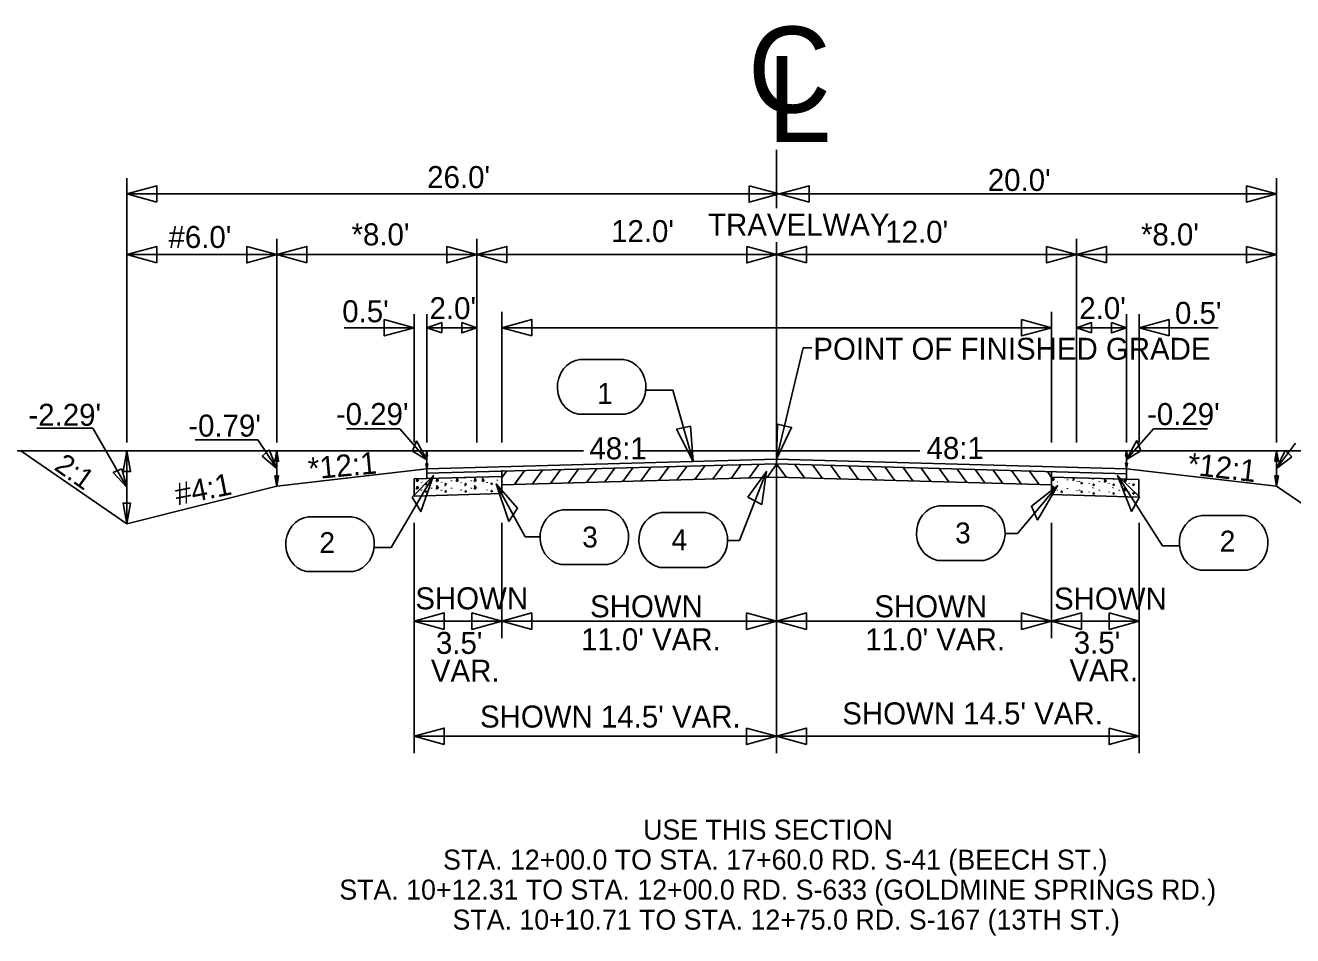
# Model space of a CAD drawing. Extents: x 2061536 to 2063199, y 948597 to 949645.
# Drawn here: x 2062001 to 2062634, y 948998 to 949454 of the extents above; entities that cross this region are included whole.
import ezdxf

# ---------------------------------------------------------------- set-up
doc = ezdxf.new("R2010")
doc.units = 0
for name, color, linetype in [('Default', 7, 'Continuous'), ('RD_TX_Drainage', 7, 'Continuous'), ('RD_TX_TypSect', 7, 'Continuous'), ('RD_XS_Base', 7, 'Continuous'), ('RD_XS_EarthShd', 7, 'Continuous'), ('RD_XS_Pave', 7, 'Continuous')]:
    doc.layers.add(name, color=color, linetype=linetype)

msp = doc.modelspace()

# ---------------------------------------------------------------- linework, layer by layer
at = {"layer": 'Default'}
for p, q in [((2062376.29, 949362.08), (2062376.29, 949391.39)), ((2062051.29, 949245.07), (2062051.29, 949377.17)), ((2062626.29, 949245.07), (2062626.29, 949377.17)), ((2062119.72, 949369.28), (2062051.29, 949369.28)), ((2062377.53, 949369.28), (2062119.72, 949369.28)), ((2062377.53, 949369.28), (2062626.29, 949369.28)), ((2062126.29, 949245.07), (2062126.29, 949346.82)), ((2062226.29, 949245.07), (2062226.29, 949346.82)), ((2062526.29, 949245.07), (2062526.29, 949346.82)), ((2062376.29, 949340.85), (2062376.29, 949345.1)), ((2062376.29, 949306.44), (2062376.29, 949340.85)), ((2062126.29, 949338.93), (2062051.29, 949338.93)), ((2062226.29, 949338.93), (2062126.29, 949338.93)), ((2062376.29, 949338.93), (2062226.29, 949338.93)), ((2062376.29, 949338.93), (2062526.29, 949338.93)), ((2062526.29, 949338.93), (2062626.29, 949338.93)), ((2062195.04, 949245.07), (2062195.04, 949309.2)), ((2062201.29, 949245.07), (2062201.29, 949309.2)), ((2062238.79, 949245.07), (2062238.79, 949310.28)), ((2062513.79, 949245.07), (2062513.79, 949310.28)), ((2062551.29, 949245.07), (2062551.29, 949309.2)), ((2062557.54, 949245.07), (2062557.54, 949309.2)), ((2062195.04, 949302.39), (2062159.95, 949302.39)), ((2062195.04, 949302.39), (2062167.38, 949302.39)), ((2062226.29, 949302.39), (2062201.29, 949302.39)), ((2062238.79, 949302.39), (2062513.79, 949302.39)), ((2062376.29, 949295.45), (2062376.29, 949306.44)), ((2062526.29, 949302.39), (2062551.29, 949302.39)), ((2062557.54, 949302.39), (2062597.15, 949302.39)), ((2062376.29, 949089.68), (2062376.29, 949295.45)), ((2062376.29, 949236.65), (2062389.59, 949292.31)), ((2062389.59, 949292.31), (2062393.83, 949292.31)), ((2062324.32, 949271.16), (2062310.37, 949271.16)), ((2062334.47, 949235.47), (2062324.32, 949271.16)), ((2062006.29, 949252.16), (2062034.34, 949252.16)), ((2062034.34, 949252.16), (2062051.29, 949222.58)), ((2062187.82, 949251.78), (2062161.2, 949251.78)), ((2062187.82, 949251.78), (2062201.29, 949236.25)), ((2062564.77, 949251.78), (2062551.29, 949236.43)), ((2062564.77, 949251.78), (2062591.72, 949251.78)), ((2062116.79, 949246.28), (2062085.44, 949246.28)), ((2062116.79, 949246.28), (2062126.29, 949231.96)), ((2062635.79, 949244.68), (2062626.29, 949231.96)), ((2062199.54, 949240.77), (2061643.36, 949240.77)), ((2062051.29, 949204.39), (2062051.29, 949240.77)), ((2062126.29, 949223.14), (2062126.29, 949240.77)), ((2062279.64, 949240.77), (2062199.54, 949240.77)), ((2062201.29, 949231.74), (2062201.29, 949240.77)), ((2062376.29, 949240.77), (2062307.2, 949240.77)), ((2062376.29, 949240.77), (2062447.94, 949240.77)), ((2062476.17, 949240.77), (2062557.9, 949240.77)), ((2062551.29, 949231.74), (2062551.29, 949240.77)), ((2062555.37, 949240.77), (2063173.98, 949240.77)), ((2062626.29, 949223.14), (2062626.29, 949240.77)), ((2062204.67, 949228.55), (2062183.53, 949192.56)), ((2062357.77, 949196.05), (2062371.14, 949230.57)), ((2062546.7, 949228.41), (2062569.22, 949193.26)), ((2062250.57, 949197.82), (2062236.04, 949224.3)), ((2062496.66, 949199.53), (2062516.81, 949223.38)), ((2062195.04, 949147.22), (2062195.04, 949204.75)), ((2062238.79, 949147.22), (2062238.79, 949204.75)), ((2062513.79, 949147.22), (2062513.79, 949204.75)), ((2062557.54, 949147.22), (2062557.54, 949204.75)), ((2062257.95, 949197.82), (2062250.57, 949197.82)), ((2062351.69, 949196.05), (2062357.77, 949196.05)), ((2062490.7, 949199.53), (2062496.66, 949199.53)), ((2062183.53, 949192.56), (2062175.04, 949192.56)), ((2062569.22, 949193.26), (2062577.71, 949193.26)), ((2062376.29, 949155.62), (2062195.04, 949155.62)), ((2062376.29, 949155.62), (2062557.54, 949155.62)), ((2062195.04, 949089.68), (2062195.04, 949147.22)), ((2062557.54, 949089.68), (2062557.54, 949147.22)), ((2062376.29, 949098.08), (2062195.04, 949098.08)), ((2062376.23, 949098.08), (2062557.54, 949098.08))]:
    msp.add_line(p, q, dxfattribs=at)
for points in [[(2062066.29, 949365.15), (2062051.29, 949369.28), (2062066.29, 949373.4)], [(2062362.53, 949373.4), (2062377.53, 949369.28), (2062362.53, 949365.15)], [(2062392.53, 949365.15), (2062377.53, 949369.28), (2062392.53, 949373.4)], [(2062611.29, 949373.4), (2062626.29, 949369.28), (2062611.29, 949365.15)], [(2062066.29, 949334.8), (2062051.29, 949338.93), (2062066.29, 949343.05)], [(2062111.29, 949343.05), (2062126.29, 949338.93), (2062111.29, 949334.8)], [(2062141.29, 949334.8), (2062126.29, 949338.93), (2062141.29, 949343.05)], [(2062211.29, 949343.05), (2062226.29, 949338.93), (2062211.29, 949334.8)], [(2062241.29, 949334.8), (2062226.29, 949338.93), (2062241.29, 949343.05)], [(2062361.29, 949343.05), (2062376.29, 949338.93), (2062361.29, 949334.8)], [(2062391.29, 949334.8), (2062376.29, 949338.93), (2062391.29, 949343.05)], [(2062511.29, 949343.05), (2062526.29, 949338.93), (2062511.29, 949334.8)], [(2062541.29, 949334.8), (2062526.29, 949338.93), (2062541.29, 949343.05)], [(2062611.29, 949343.05), (2062626.29, 949338.93), (2062611.29, 949334.8)], [(2062180.04, 949306.52), (2062195.04, 949302.39), (2062180.04, 949298.27)], [(2062253.79, 949298.27), (2062238.79, 949302.39), (2062253.79, 949306.52)], [(2062498.79, 949306.52), (2062513.79, 949302.39), (2062498.79, 949298.27)], [(2062572.54, 949298.27), (2062557.54, 949302.39), (2062572.54, 949306.52)], [(2062333.12, 949253.11), (2062334.47, 949235.47), (2062326.22, 949251.59)], [(2062376.78, 949254.19), (2062376.29, 949236.65), (2062383.79, 949252.52)], [(2062196.19, 949245.8), (2062201.29, 949236.25), (2062194.24, 949240.71)], [(2062556.45, 949245.95), (2062551.29, 949236.43), (2062558.37, 949240.84)], [(2062118.94, 949238.19), (2062126.29, 949231.96), (2062122.47, 949241.26)], [(2062633.98, 949237.77), (2062626.29, 949231.96), (2062630.63, 949241.03)], [(2062048.78, 949231.88), (2062051.29, 949222.58), (2062044.5, 949229.99)], [(2062193.99, 949217.61), (2062204.67, 949228.55), (2062198.27, 949210.41)], [(2062361.92, 949217.58), (2062371.14, 949230.57), (2062368.94, 949214.06)], [(2062557.8, 949217.89), (2062546.7, 949228.41), (2062553.8, 949210.53)], [(2062242.37, 949205.49), (2062236.04, 949224.3), (2062246.7, 949212.17)], [(2062506.69, 949206.08), (2062516.81, 949223.38), (2062503.65, 949213.12)], [(2062210.04, 949151.5), (2062195.04, 949155.62), (2062210.04, 949159.75)], [(2062223.79, 949159.75), (2062238.79, 949155.62), (2062223.79, 949151.5)], [(2062253.79, 949151.5), (2062238.79, 949155.62), (2062253.79, 949159.75)], [(2062361.23, 949159.75), (2062376.23, 949155.62), (2062361.23, 949151.5)], [(2062391.23, 949151.5), (2062376.23, 949155.62), (2062391.23, 949159.75)], [(2062498.79, 949159.75), (2062513.79, 949155.62), (2062498.79, 949151.5)], [(2062528.79, 949151.5), (2062513.79, 949155.62), (2062528.79, 949159.75)], [(2062542.54, 949159.75), (2062557.54, 949155.62), (2062542.54, 949151.5)], [(2062210.04, 949093.96), (2062195.04, 949098.08), (2062210.04, 949102.21)], [(2062361.23, 949102.21), (2062376.23, 949098.08), (2062361.23, 949093.96)], [(2062391.23, 949093.96), (2062376.23, 949098.08), (2062391.23, 949102.21)], [(2062542.54, 949102.21), (2062557.54, 949098.08), (2062542.54, 949093.96)]]:
    msp.add_lwpolyline(points, close=True, dxfattribs=at)
for points in [[(2062277.84, 949286.44), (2062299.75, 949286.44)], [(2062300.43, 949259.09), (2062277.16, 949259.09)], [(2062457.42, 949213.39), (2062479.33, 949213.39)], [(2062163.91, 949207.83), (2062141.99, 949207.83)], [(2062291.07, 949211.34), (2062269.16, 949211.34)], [(2062318.61, 949209.91), (2062340.52, 949209.91)], [(2062588.84, 949208.54), (2062610.76, 949208.54)], [(2062268.48, 949184), (2062291.75, 949184)], [(2062341.2, 949182.57), (2062317.93, 949182.57)], [(2062480.01, 949186.04), (2062456.74, 949186.04)], [(2062611.43, 949181.19), (2062588.16, 949181.19)], [(2062141.32, 949180.49), (2062164.59, 949180.49)]]:
    msp.add_lwpolyline(points, dxfattribs=at)
for centre, major_axis, start_param, end_param in [((2062279.17, 949272.71), (0, 13.8), 6.17662, 9.263617), ((2062298.42, 949272.71), (0, 13.8), 3.302754, 6.389751), ((2062458.75, 949199.66), (0, 13.8), 6.17662, 9.263617), ((2062478, 949199.66), (0, 13.8), 3.302754, 6.389751), ((2062143.33, 949194.11), (0, -13.8), 3.035027, 6.122024), ((2062162.57, 949194.11), (0, -13.8), 0.161161, 3.248158), ((2062270.49, 949197.62), (0, -13.8), 3.035027, 6.122024), ((2062289.74, 949197.62), (0, -13.8), 0.161161, 3.248158), ((2062319.95, 949196.19), (0, 13.8), 6.17662, 9.263617), ((2062339.19, 949196.19), (0, 13.8), 3.302754, 6.389751), ((2062590.18, 949194.81), (0, 13.8), 6.17662, 9.263617), ((2062609.42, 949194.81), (0, 13.8), 3.302754, 6.389751)]:
    msp.add_ellipse(centre, major_axis=major_axis, ratio=0.909091, start_param=start_param, end_param=end_param, dxfattribs=at)
at = {"layer": 'RD_TX_Drainage'}
for points in [[(2062208.79, 949299.81), (2062201.29, 949302.39), (2062208.79, 949304.97)], [(2062218.79, 949304.97), (2062226.29, 949302.39), (2062218.79, 949299.81)], [(2062533.79, 949299.81), (2062526.29, 949302.39), (2062533.79, 949304.97)], [(2062543.79, 949304.97), (2062551.29, 949302.39), (2062543.79, 949299.81)], [(2062049.42, 949230.46), (2062051.29, 949240.77), (2062053.17, 949230.46)], [(2062125.35, 949235.62), (2062126.29, 949240.77), (2062127.23, 949235.62)], [(2062200.82, 949238.2), (2062201.29, 949240.77), (2062201.76, 949238.2)], [(2062550.82, 949238.2), (2062551.29, 949240.77), (2062551.76, 949238.2)], [(2062625.35, 949235.62), (2062626.29, 949240.77), (2062627.23, 949235.62)], [(2062201.77, 949234.31), (2062201.3, 949231.74), (2062200.83, 949234.31)], [(2062551.76, 949234.67), (2062551.29, 949232.09), (2062550.82, 949234.67)], [(2062127.23, 949228.3), (2062126.29, 949223.14), (2062125.35, 949228.3)], [(2062627.23, 949228.3), (2062626.29, 949223.14), (2062625.35, 949228.3)], [(2062053.17, 949214.7), (2062051.29, 949204.39), (2062049.42, 949214.7)]]:
    msp.add_lwpolyline(points, close=True, dxfattribs=at)
at = {"layer": 'RD_XS_Base'}
for p, q in [((2062272.25, 949224.79), (2062277.1, 949231.46)), ((2062281.27, 949225.04), (2062286.12, 949231.71)), ((2062290.29, 949225.29), (2062295.15, 949231.97)), ((2062299.32, 949225.55), (2062304.28, 949232.37)), ((2062308.34, 949225.8), (2062313.29, 949232.6)), ((2062317.36, 949226.05), (2062322.29, 949232.83)), ((2062326.39, 949226.31), (2062331.3, 949233.07)), ((2062335.41, 949226.56), (2062340.31, 949233.3)), ((2062344.43, 949226.81), (2062349.32, 949233.54)), ((2062353.46, 949227.07), (2062358.33, 949233.77)), ((2062362.48, 949227.32), (2062367.34, 949234.01)), ((2062371.5, 949227.57), (2062376.29, 949234.16)), ((2062376.29, 949234.32), (2062381.2, 949227.57)), ((2062385.37, 949233.99), (2062390.22, 949227.32)), ((2062394.39, 949233.73), (2062399.24, 949227.06)), ((2062403.42, 949233.48), (2062408.27, 949226.81)), ((2062412.44, 949233.23), (2062417.29, 949226.56)), ((2062421.46, 949232.97), (2062426.31, 949226.3)), ((2062430.49, 949232.72), (2062435.34, 949226.05)), ((2062439.51, 949232.47), (2062444.36, 949225.8)), ((2062448.53, 949232.21), (2062453.38, 949225.54)), ((2062457.56, 949231.96), (2062462.41, 949225.29)), ((2062466.58, 949231.71), (2062471.43, 949225.04)), ((2062475.6, 949231.45), (2062480.45, 949224.78)), ((2062238.79, 949227.99), (2062195.05, 949226.76)), ((2062195.05, 949226.76), (2062195.05, 949218.19)), ((2062198.63, 949225.01), (2062198.65, 949224.76)), ((2062200.49, 949226.91), (2062200.49, 949226.91)), ((2062203.65, 949225.73), (2062203.74, 949225.99)), ((2062208.6, 949225.01), (2062208.62, 949224.76)), ((2062210.46, 949226.91), (2062210.54, 949227.16)), ((2062213.62, 949225.73), (2062213.71, 949225.99)), ((2062218.57, 949225.01), (2062218.59, 949224.76)), ((2062220.43, 949226.91), (2062220.51, 949227.16)), ((2062223.59, 949225.73), (2062223.68, 949225.99)), ((2062231.53, 949225.09), (2062231.56, 949224.84)), ((2062236.54, 949226), (2062236.62, 949226.26)), ((2062238.79, 949219.41), (2062238.79, 949231.09)), ((2062238.79, 949227.4), (2062241.01, 949230.45)), ((2062376.29, 949227.71), (2062238.79, 949223.85)), ((2062245.18, 949224.03), (2062250.03, 949230.7)), ((2062245.75, 949224.81), (2062250.03, 949230.7)), ((2062254.2, 949224.28), (2062259.05, 949230.95)), ((2062263.23, 949224.53), (2062268.08, 949231.21)), ((2062263.79, 949225.31), (2062268.08, 949231.21)), ((2062376.29, 949227.71), (2062513.79, 949223.85)), ((2062484.62, 949231.2), (2062488.79, 949225.47)), ((2062484.62, 949231.2), (2062489.47, 949224.53)), ((2062493.65, 949230.95), (2062498.5, 949224.28)), ((2062502.67, 949230.69), (2062507.52, 949224.03)), ((2062511.69, 949230.44), (2062513.79, 949227.56)), ((2062513.79, 949218.93), (2062513.79, 949230.38)), ((2062557.47, 949226.41), (2062513.79, 949227.63)), ((2062516.63, 949225.49), (2062516.65, 949225.24)), ((2062521.65, 949226.21), (2062521.74, 949226.47)), ((2062526.6, 949225.49), (2062526.62, 949225.24)), ((2062527.68, 949225.38), (2062527.76, 949225.64)), ((2062534.48, 949226.56), (2062534.57, 949226.81)), ((2062537.65, 949225.38), (2062537.73, 949225.64)), ((2062544.45, 949226.56), (2062544.52, 949226.77)), ((2062547.62, 949225.38), (2062547.7, 949225.64)), ((2062557.47, 949217.7), (2062557.47, 949226.41)), ((2062195.05, 949218.19), (2062238.79, 949219.41)), ((2062198.63, 949221.29), (2062198.65, 949221.03)), ((2062200.49, 949223.18), (2062200.49, 949223.19)), ((2062203.65, 949222.01), (2062203.74, 949222.27)), ((2062208.6, 949221.29), (2062208.62, 949221.03)), ((2062210.46, 949223.18), (2062210.54, 949223.44)), ((2062213.62, 949222.01), (2062213.71, 949222.27)), ((2062218.57, 949221.29), (2062218.59, 949221.03)), ((2062220.43, 949223.18), (2062220.51, 949223.44)), ((2062223.59, 949222.01), (2062223.68, 949222.27)), ((2062231.53, 949221.37), (2062231.56, 949221.12)), ((2062236.54, 949222.28), (2062236.62, 949222.54)), ((2062557.47, 949217.7), (2062513.79, 949218.93)), ((2062516.63, 949221.17), (2062516.65, 949220.91)), ((2062521.65, 949221.89), (2062521.74, 949222.14)), ((2062526.6, 949221.17), (2062526.62, 949220.91)), ((2062527.68, 949221.06), (2062527.76, 949221.32)), ((2062532.62, 949224.66), (2062532.65, 949224.41)), ((2062532.62, 949220.34), (2062532.65, 949220.08)), ((2062534.48, 949222.23), (2062534.57, 949222.49)), ((2062537.65, 949221.06), (2062537.73, 949221.32)), ((2062542.59, 949224.66), (2062542.62, 949224.41)), ((2062542.59, 949220.34), (2062542.62, 949220.08)), ((2062544.45, 949222.23), (2062544.52, 949222.44)), ((2062547.62, 949221.06), (2062547.7, 949221.32)), ((2062552.56, 949224.66), (2062552.59, 949224.41)), ((2062552.56, 949220.34), (2062552.59, 949220.08))]:
    msp.add_line(p, q, dxfattribs=at)
for points in [[(2062196.22, 949225.44), (2062196.35, 949226.8)], [(2062196.57, 949226.8), (2062197.13, 949226.01), (2062196.24, 949225.45)], [(2062206.19, 949225.44), (2062206.35, 949227.07), (2062207.1, 949226.01), (2062206.21, 949225.45)], [(2062216.16, 949225.44), (2062216.32, 949227.07), (2062217.07, 949226.01), (2062216.18, 949225.45)], [(2062225.1, 949225.44), (2062225.27, 949227.07), (2062226.01, 949226.01), (2062225.12, 949225.45)], [(2062229.11, 949225.43), (2062229.24, 949227.07), (2062230.01, 949226.04), (2062229.13, 949225.44)], [(2062514.22, 949225.92), (2062514.38, 949227.55), (2062515.13, 949226.49), (2062514.24, 949225.93)], [(2062524.44, 949227.43), (2062525.1, 949226.49), (2062524.21, 949225.93)], [(2062528.5, 949224.38), (2062528.75, 949225.1), (2062529.17, 949224.67), (2062528.5, 949224.38)], [(2062540.18, 949225.09), (2062540.34, 949226.72), (2062541.09, 949225.66), (2062540.2, 949225.1)], [(2062550.15, 949225.09), (2062550.3, 949226.61)], [(2062550.4, 949226.6), (2062551.06, 949225.66), (2062550.17, 949225.1)], [(2062196.22, 949221.71), (2062196.35, 949223.07)], [(2062196.57, 949223.08), (2062197.13, 949222.29), (2062196.24, 949221.72)], [(2062200.53, 949223.9), (2062200.78, 949224.62), (2062201.2, 949224.19), (2062200.53, 949223.9)], [(2062200.53, 949220.18), (2062200.78, 949220.89), (2062201.2, 949220.46), (2062200.53, 949220.18)], [(2062206.19, 949221.71), (2062206.35, 949223.35), (2062207.1, 949222.29), (2062206.21, 949221.72)], [(2062210.5, 949223.9), (2062210.75, 949224.62), (2062211.17, 949224.19), (2062210.5, 949223.9)], [(2062210.5, 949220.18), (2062210.75, 949220.89), (2062211.17, 949220.46), (2062210.5, 949220.18)], [(2062220.47, 949223.9), (2062220.72, 949224.62), (2062221.14, 949224.19), (2062220.47, 949223.9)], [(2062220.47, 949220.18), (2062220.72, 949220.89), (2062221.14, 949220.46), (2062220.47, 949220.18)], [(2062225.1, 949221.71), (2062225.27, 949223.35), (2062226.01, 949222.29), (2062225.12, 949221.72)], [(2062233.46, 949224.05), (2062233.69, 949224.78), (2062234.12, 949224.37), (2062233.46, 949224.05)], [(2062233.46, 949220.33), (2062233.69, 949221.06), (2062234.12, 949220.64), (2062233.46, 949220.33)], [(2062514.22, 949221.59), (2062514.38, 949223.23), (2062515.13, 949222.17), (2062514.24, 949221.6)], [(2062518.53, 949220.05), (2062518.78, 949220.77), (2062519.2, 949220.34), (2062518.53, 949220.05)], [(2062528.5, 949220.05), (2062528.75, 949220.77), (2062529.17, 949220.34), (2062528.5, 949220.05)], [(2062534.52, 949223.55), (2062534.77, 949224.27), (2062535.19, 949223.84), (2062534.52, 949223.55)], [(2062534.52, 949219.23), (2062534.77, 949219.94), (2062535.19, 949219.51), (2062534.52, 949219.23)], [(2062544.49, 949223.55), (2062544.74, 949224.27), (2062545.16, 949223.84), (2062544.49, 949223.55)], [(2062544.49, 949219.23), (2062544.74, 949219.94), (2062545.16, 949219.51), (2062544.49, 949219.23)], [(2062550.15, 949220.76), (2062550.3, 949222.28)], [(2062550.4, 949222.28), (2062551.06, 949221.34), (2062550.17, 949220.77)], [(2062554.46, 949223.55), (2062554.71, 949224.27), (2062555.13, 949223.84), (2062554.46, 949223.55)], [(2062554.46, 949219.23), (2062554.71, 949219.94), (2062555.13, 949219.51), (2062554.46, 949219.23)]]:
    msp.add_lwpolyline(points, dxfattribs=at)
at = {"layer": 'RD_XS_EarthShd'}
for p, q in [((2062051.29, 949204.39), (2061998.37, 949240.77)), ((2062201.3, 949231.74), (2062126.29, 949223.14)), ((2062551.29, 949231.74), (2062626.29, 949223.14)), ((2062051.29, 949204.39), (2062126.29, 949223.14)), ((2062626.29, 949223.14), (2062751.29, 949137.21))]:
    msp.add_line(p, q, dxfattribs=at)
at = {"layer": 'RD_XS_Pave'}
for p, q in [((2062201.3, 949231.74), (2062376.29, 949236.65)), ((2062376.29, 949236.65), (2062201.3, 949231.74)), ((2062376.26, 949234.24), (2062201.3, 949229.68)), ((2062201.3, 949229.68), (2062201.3, 949231.74)), ((2062376.22, 949234.24), (2062551.22, 949229.33)), ((2062551.22, 949229.33), (2062376.26, 949234.24)), ((2062376.29, 949236.65), (2062551.29, 949231.74)), ((2062376.29, 949236.65), (2062551.29, 949231.74)), ((2062551.29, 949231.74), (2062551.22, 949229.33)), ((2062201.3, 949229.68), (2062201.3, 949226.93)), ((2062551.22, 949229.33), (2062551.22, 949226.58))]:
    msp.add_line(p, q, dxfattribs=at)

# ---------------------------------------------------------------- texts
at = {"layer": 'Default'}
for s, height, p in [('C', 42.97, (2062361.87, 949409.96)), ('L', 42.97, (2062371.61, 949395.22)), ('1', 10.45, (2062286.53, 949264.26)), ("-2.29'", 11, (2062002.11, 949253.34)), ("-0.29'", 11, (2062561.52, 949253.72)), ('4', 10.45, (2062323.74, 949191.08)), ('3', 10.45, (2062465.54, 949194.55)), ('2', 10.45, (2062597.87, 949190.43))]:
    msp.add_text(s, height=height, dxfattribs=at).set_placement(p)
for s, height, p in [("-0.29'", 11, (2062155.86, 949253.72)), ("-0.79'", 11, (2062082.04, 949247.94)), ('2', 10.45, (2062147.63, 949189.72)), ('3', 10.45, (2062279.06, 949192.51))]:
    msp.add_text(s, height=height, rotation=360, dxfattribs=at).set_placement(p)
at = {"layer": 'RD_TX_TypSect'}
for s, height, p in [("26.0' ", 11, (2062201.53, 949372.2)), ("20.0' ", 11, (2062481.88, 949370.77)), ('TRAVELWAY', 11, (2062342, 949348.4)), ("#6.0'", 11, (2062072.16, 949342.26)), ("*8.0' ", 11, (2062163.7, 949343.53)), ("12.0' ", 11, (2062293.5, 949345.18)), ("12.0' ", 11, (2062430.63, 949344.83)), ("*8.0' ", 11, (2062558.47, 949343.53)), ("0.5'", 11, (2062159.05, 949305.12)), ("2.0'", 11, (2062202.71, 949306.66)), ("2.0'", 11, (2062527.65, 949306.69)), ("0.5'", 11, (2062575.49, 949304.31)), ('POINT OF FINISHED GRADE', 11, (2062394.66, 949286.34)), ('48:1', 11, (2062282.66, 949236.59)), ('48:1', 11, (2062451.27, 949236.72)), ('SHOWN', 11, (2062195.59, 949161.57)), ('SHOWN ', 11, (2062283, 949157.57)), ('SHOWN ', 11, (2062425.15, 949157.57)), ('SHOWN', 11, (2062514.99, 949161.45)), ("3.5'", 11, (2062205.9, 949139.29)), ("11.0' VAR.", 11, (2062278.47, 949141.07)), ("11.0' VAR.", 11, (2062420.62, 949141.07)), ("3.5'", 11, (2062524.87, 949139.44)), ('VAR.', 11, (2062203.39, 949125.38)), ('VAR.', 11, (2062522.7, 949125.63)), ("SHOWN 14.5' VAR.", 11, (2062227.95, 949102.46)), ("SHOWN 14.5' VAR.", 11, (2062409.1, 949104.05)), ('USE THIS SECTION', 10, (2062309.51, 949046.42)), ('STA. 12+00.0 TO STA. 17+60.0 RD. S-41 (BEECH ST.)', 10, (2062209.47, 949031.42)), ('STA. 10+12.31 TO STA. 12+00.0 RD. S-633 (GOLDMINE SPRINGS RD.)', 10, (2062157.58, 949016.42)), ('STA. 10+10.71 TO STA. 12+75.0 RD. S-167 (13TH ST.)', 10, (2062214.2, 949001.42))]:
    msp.add_text(s, height=height, dxfattribs=at).set_placement(p)
for s, height, rotation, p in [('2:1', 10.309, 324.82741, (2062014.47, 949231.76)), ('*12:1', 10.985, 5.22382, (2062142.51, 949226.4)), ('*12:1', 10.976, 353.43139, (2062581.36, 949229.07)), ('#4:1', 10.928, 11.30971, (2062076.54, 949213.54))]:
    msp.add_text(s, height=height, rotation=rotation, dxfattribs=at).set_placement(p)

doc.saveas('drawing.dxf')
